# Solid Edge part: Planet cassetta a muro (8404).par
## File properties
Title: Planet cassetta a muro
Author: DESYS
Template: Normal.par
Last saved by: s.pallini
Revision: 38
Application: Solid Edge
Tipo di contenuto documento: 0
Precisione: 0,990
Document Number: 8404
Revision: 0
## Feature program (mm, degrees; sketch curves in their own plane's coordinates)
sketch for "ExtrudedProtrusion_1" plane through (0, 0, 0) normal (0, -1, 0) x-axis (1, 0, 0)
  line (-190, -53.3265) -> (190, -53.3265)
  line (190, -53.3265) -> (190, 886.6735)
  line (190, 886.6735) -> (-190, 886.6735)
  line (-190, -53.3265) -> (-190, 886.6735)
  dimension (linear) = 190
  dimension (linear) = 190
extrude "ExtrudedProtrusion_1" add finite 145 along -normal
sketch for "ExtrudedCutout_1" plane through (0, 145, 421.6735) normal (0, 1, 0) x-axis (-1, 0, 0)
  line (-155, 450) -> (-155, -430)
  line (-155, -430) -> (155, -430)
  line (155, 450) -> (155, -430)
  line (-155, 450) -> (155, 450)
extrude "ExtrudedCutout_1" cut finite 120 along -normal
sketch for "unnamed Cutout 1" plane through (0, 25, 441.6735) normal (0, 1, 0) x-axis (-1, 0, 0)
  line (-82.5, -450) -> (-82.5, -192.5)
  arc centre (-60, -91.474) radius 35 from (-42.1277, -121.5669) to (-25, -91.474) ccw
  line (-25, -65) -> (-25, -91.474)
  line (25, -65) -> (25, -91.474)
  arc centre (60, -91.474) radius 35 from (25, -91.474) to (42.1277, -121.5669) ccw
  arc centre (0, -192.5) radius 82.5 from (42.1277, -121.5669) to (82.5, -192.5) cw
  line (82.5, -192.5) -> (82.5, -450)
  line (82.5, -450) -> (-82.5, -450)
extrude "unnamed Cutout 1" cut through along -normal
sketch for "unnamed Cutout 2" plane through (0, 70, -53.3265) normal (0, 0, -1) x-axis (-1, 0, 0)
  line (-110, -40) -> (110, -40)
  arc centre (110, -20) radius 20 from (110, -40) to (130, -20) ccw
  line (130, -20) -> (130, 20)
  arc centre (110, 20) radius 20 from (130, 20) to (110, 40) ccw
  line (110, 40) -> (-110, 40)
  arc centre (-110, 20) radius 20 from (-130, 20) to (-110, 40) cw
  line (-130, 20) -> (-130, -20)
  arc centre (-110, -20) radius 20 from (-130, -20) to (-110, -40) ccw
  dimension (linear) = 110
  dimension (linear) = 130
extrude "unnamed Cutout 2" cut through along -normal
sketch for "Foro_1" plane through (0, 0, 0) normal (0, 0, 1) x-axis (1, 0, 0)
  hole centre (0, 95) bore radius 20
hole "Foro_1" diameter 40 through
sketch for "ExtrudedCutout_4" #1 plane through (0, 145, 421.6735) normal (0, 1, 0) x-axis (-1, 0, 0)
  line (160, 434.7992) -> (160, -442.9749)
  arc centre (170, -442.9749) radius 10 from (179.9705, -443.7424) to (160, -442.9749) cw
  line (169.9752, 435.2962) -> (179.9705, -443.7424)
  arc centre (165, 434.7992) radius 5 from (160, 434.7992) to (169.9752, 435.2962) cw
sketch for "ExtrudedCutout_4" #2 plane through (0, 145, 421.6735) normal (0, 1, 0) x-axis (-1, 0, 0)
  line (-122.5, -470) -> (122.5, -470)
  arc centre (122.5, -465) radius 5 from (122.5, -470) to (127.5, -465) ccw
  line (127.5, -465) -> (127.5, -440)
  arc centre (122.5, -440) radius 5 from (122.5, -435) to (127.5, -440) cw
  line (122.5, -435) -> (-122.5, -435)
  arc centre (-122.5, -440) radius 5 from (-122.5, -435) to (-127.5, -440) ccw
  line (-127.5, -440) -> (-127.5, -465)
  arc centre (-122.5, -465) radius 5 from (-127.5, -465) to (-122.5, -470) ccw
sketch for "ExtrudedCutout_4" #3 plane through (0, 145, 421.6735) normal (0, 1, 0) x-axis (-1, 0, 0)
  line (-160, 434.7992) -> (-160, -442.9749)
  arc centre (-170, -442.9749) radius 10 from (-179.9705, -443.7424) to (-160, -442.9749) ccw
  line (-169.9752, 435.2962) -> (-179.9705, -443.7424)
  arc centre (-165, 434.7992) radius 5 from (-160, 434.7992) to (-169.9752, 435.2962) ccw
extrude "ExtrudedCutout_4" cut finite 8 along -normal
sketch for "ExtrudedProtrusion_2" plane through (0, 25, 441.6735) normal (0, 1, 0) x-axis (0, 0, 1)
  line (-192.5, 82.5) -> (-430, 82.5)
  line (-430, 92.5) -> (-430, 82.5)
  line (-192.5, 92.5) -> (-430, 92.5)
  arc centre (-192.5, 0) radius 92.5 from (-112.9689, 47.234) to (-192.5, 92.5) ccw
  arc centre (-91.474, 60) radius 25 from (-91.474, 35) to (-112.9689, 47.234) cw
  line (-65, 35) -> (-91.474, 35)
  arc centre (-65, 0) radius 35 from (-65, -35) to (-65, 35) ccw
  line (-91.474, -35) -> (-65, -35)
  arc centre (-91.474, -60) radius 25 from (-112.9689, -47.234) to (-91.474, -35) cw
  arc centre (-192.5, 0) radius 92.5 from (-192.5, -92.5) to (-112.9689, -47.234) ccw
  line (-422.5, -92.5) -> (-192.5, -92.5)
  line (-422.5, -82.5) -> (-422.5, -92.5)
  line (-192.5, -82.5) -> (-422.5, -82.5)
  arc centre (-192.5, 0) radius 82.5 from (-192.5, -82.5) to (-121.5668, -42.1277) ccw
  arc centre (-91.474, -60) radius 35 from (-121.5668, -42.1277) to (-91.474, -25) cw
  line (-91.474, -25) -> (-65, -25)
  arc centre (-65, 0) radius 25 from (-65, -25) to (-65, 25) ccw
  line (-65, 25) -> (-91.474, 25)
  arc centre (-91.474, 60) radius 35 from (-91.474, 25) to (-121.5668, 42.1277) cw
  arc centre (-192.5, 0) radius 82.5 from (-121.5668, 42.1277) to (-192.5, 82.5) ccw
extrude "ExtrudedProtrusion_2" add finite 10 along +normal
fillet "Rotondo_1" radius 5
draft "Draft_1"  Angles1 = 10 deg
sketch for "unnamed Cutout 3" plane through (0, 72.5, 886.6735) normal (0, 0, 1) x-axis (-1, 0, 0)
extrude "unnamed Cutout 3" cut through along -normal
fillet "Rotondo_6" radius 10
fillet "Rotondo_7" radius 5
sketch for "unnamed Cutout 4" plane through (0, 0, 416.6735) normal (0, -1, 0) x-axis (1, 0, 0)
  arc centre (0, -167.5) radius 82.5 from (-82.5, -167.5) to (-42.1277, -96.5669) cw
  arc centre (-60, -66.474) radius 35 from (-42.1277, -96.5669) to (-27.3734, -79.1431) ccw
  arc centre (-60, -66.474) radius 35 from (-25, -66.474) to (-27.3734, -79.1431) cw
  line (-25, -30) -> (-25, -66.474)
  arc centre (0, -30) radius 25 from (25, -30) to (-25, -30) ccw
  line (25, -66.474) -> (25, -30)
  arc centre (60, -66.474) radius 35 from (27.3734, -79.1431) to (25, -66.474) cw
  arc centre (60, -66.474) radius 35 from (42.1277, -96.5669) to (27.3734, -79.1431) cw
  arc centre (0, -167.5) radius 82.5 from (42.1277, -96.5669) to (82.5, -167.5) cw
  line (-82.5, -167.5) -> (82.5, -167.5)
extrude "unnamed Cutout 4" cut through along -normal
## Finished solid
Body 1: solid body, 126 faces, 303 edges, 176 vertices.
  Faces by surface: cylinder 59, plane 38, torus 25, sphere 4
  Edges by curve: line 160, circle 135, ellipse 4, intersection 4
Bounding box of the edges (mm; curved faces can reach further): 380.000 x 145.000 x 940.000, from (-190, 0, -53.3265) to (190, 145, 886.6735).
Cylindrical faces by radius (mm): R5 x35, R10 x7, R20 x5, R25 x3, R35 x3, R55 x2, R82.5 x2, R92.5 x2
Toroidal faces (ring radius, tube radius in mm): R10 r5 x6, R15 r5 x2, R25 r5 x8, R30 r5 x3, R50 r5 x4, R87.5 r5 x2
Spherical faces by radius (mm): R5 x2, R10 x2
Planar faces by outward normal: +x 8, +y 7, +z 4, -x 8, -y 2, -z 5, oblique 4
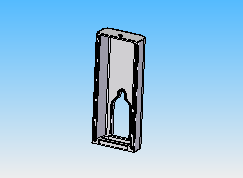
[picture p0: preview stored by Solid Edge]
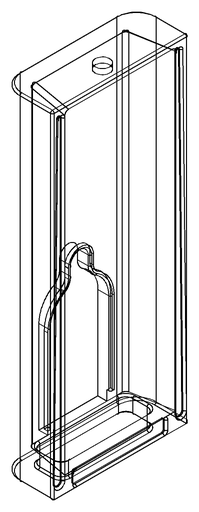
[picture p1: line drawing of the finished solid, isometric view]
